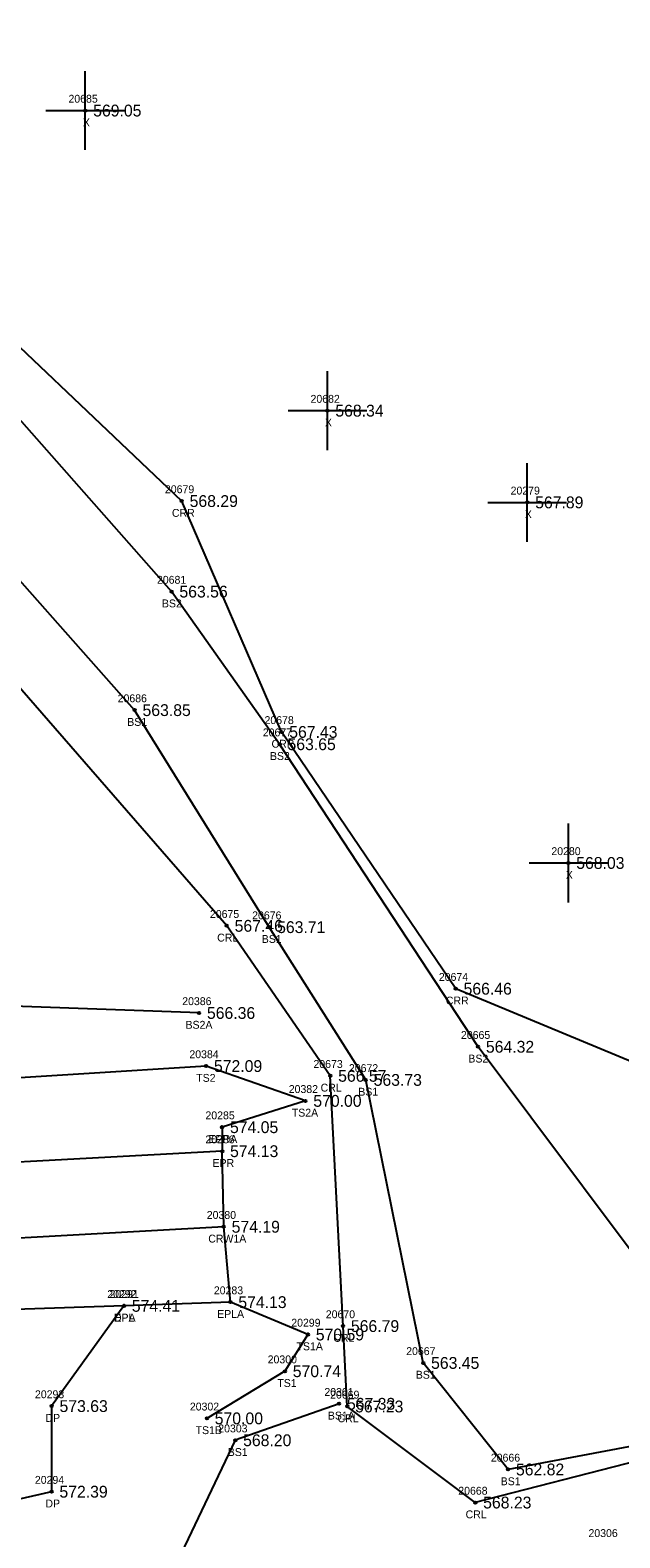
# Model space of a CAD drawing. Extents: x 1530159 to 1531652, y 877045 to 877724.
# Drawn here: x 1530840.9 to 1530915.9, y 877231.5 to 877423 of the extents above; entities that cross this region are included whole.
import ezdxf

# ---------------------------------------------------------------- set-up
doc = ezdxf.new("R2010")
doc.units = 0
for name, color, linetype in [('RD_DTM_BkLn1', 7, 'Continuous'), ('RD_DTM_BkLn2', 7, 'Continuous'), ('RD_DTM_BkLn_txCode', 7, 'Continuous'), ('RD_EX_Driveway', 7, 'Continuous'), ('RD_EX_Driveway_txCode', 7, 'Continuous'), ('RD_EX_H2O', 7, 'Continuous'), ('RD_EX_H2O_txCode', 7, 'Continuous'), ('RD_EX_Misc', 7, 'Continuous'), ('RD_EX_Misc_txCode', 7, 'Continuous'), ('RD_EX_Road', 7, 'Continuous'), ('RD_EX_Road_txCode', 7, 'Continuous'), ('RD_EX_TX_Driveway_ELEV', 7, 'Continuous'), ('RD_EX_TX_H2O_ELEV', 7, 'Continuous'), ('RD_EX_TX_Misc_ELEV', 7, 'Continuous'), ('RD_EX_TX_Road_ELEV', 7, 'Continuous'), ('RD_HC_Survey_ELEV', 7, 'Continuous'), ('RD_HC_Survey_txCode', 7, 'Continuous'), ('RD_SMD_Locator', 7, 'Continuous')]:
    doc.layers.add(name, color=color, linetype=linetype)

msp = doc.modelspace()

# ---------------------------------------------------------------- linework, layer by layer
at = {"layer": 'RD_DTM_BkLn1'}
msp.add_lwpolyline([(1530865.56, 877271.01), (1530814.96, 877268.2), (1530763.15, 877267.89), (1530711.13, 877268.14), (1530659.67, 877269.22), (1530608.85, 877271.65), (1530559.07, 877277.33), (1530509.18, 877284.07), (1530458.44, 877292.62), (1530408.04, 877304.59), (1530358.54, 877316.67), (1530308.57, 877330.02), (1530250.23, 877350.32), (1530188.17, 877372.62)], dxfattribs=at)
at = {"layer": 'RD_DTM_BkLn2'}
for points in [[(1530978.51, 877193.14), (1530957.83, 877217.34), (1530939.69, 877236.27), (1530919.92, 877243.6), (1530901.7, 877240.19), (1530890.91, 877253.72), (1530883.61, 877289.66), (1530871.34, 877309.06), (1530854.23, 877336.62), (1530832.44, 877361.15), (1530819.05, 877374.38), (1530808.85, 877385.69), (1530794.67, 877405.25), (1530798.76, 877416.08), (1530761.4, 877471.05), (1530729.88, 877527.47), (1530702.64, 877561.57), (1530689.57, 877599.12), (1530672.36, 877642.36), (1530634.08, 877679.71), (1530613.02, 877709.76)], [(1530924.53, 877258.32), (1530897.88, 877293.87), (1530872.66, 877332.29), (1530858.92, 877351.67), (1530825.26, 877389.74), (1530809.31, 877429.86), (1530783.89, 877460.41), (1530770.73, 877490.54), (1530744.62, 877534.44), (1530713.25, 877572.12), (1530699.86, 877617.16), (1530688.52, 877646.11), (1530631.13, 877700.3)], [(1530875.94, 877287), (1530863.31, 877291.42), (1530814.58, 877288.36), (1530806.87, 877291), (1530801.27, 877299.11), (1530795.25, 877327.46)], [(1530862.42, 877298.16), (1530816.3, 877299.84), (1530808.21, 877302.66), (1530797.14, 877327.67)], [(1530875.94, 877287), (1530865.35, 877283.66)], [(1530876.26, 877257.33), (1530866.41, 877261.44), (1530865.56, 877271.01), (1530865.36, 877280.61)], [(1530876.26, 877257.33), (1530873.33, 877252.67), (1530863.41, 877246.68)], [(1530880.22, 877248.53), (1530867.02, 877243.9), (1530858.87, 877226.87)]]:
    msp.add_lwpolyline(points, dxfattribs=at)
at = {"layer": 'RD_EX_Driveway'}
msp.add_lwpolyline([(1530852.87, 877260.97), (1530843.68, 877248.24), (1530843.67, 877237.37), (1530832.46, 877234.81), (1530825.81, 877245.01), (1530806.23, 877259.4)], dxfattribs=at)
at = {"layer": 'RD_EX_H2O'}
for points in [[(1530922.5, 877289.86), (1530895.04, 877301.24), (1530872.88, 877333.85), (1530860.22, 877363.17), (1530828.43, 877393.28), (1530808.3, 877433.62), (1530784.24, 877462.07), (1530773.36, 877492.12), (1530746.47, 877535.88), (1530723.52, 877580.98), (1530706.2, 877619.34), (1530689.1, 877649.27), (1530633.62, 877702.51)], [(1530972.1, 877196.48), (1530925.87, 877229.17), (1530918.34, 877241.35), (1530897.53, 877235.99), (1530881.25, 877248.19), (1530880.72, 877258.4), (1530879.1, 877290.18), (1530865.94, 877309.23), (1530832.49, 877347.64), (1530816.44, 877373.18)]]:
    msp.add_lwpolyline(points, dxfattribs=at)
at = {"layer": 'RD_EX_Misc'}
for p, q in [((1530847.96, 877407.76), (1530847.96, 877417.76)), ((1530842.96, 877412.76), (1530852.96, 877412.76)), ((1530878.74, 877369.65), (1530878.74, 877379.65)), ((1530873.74, 877374.65), (1530883.74, 877374.65)), ((1530904.14, 877358), (1530904.14, 877368)), ((1530899.14, 877363), (1530909.14, 877363)), ((1530909.36, 877312.21), (1530909.36, 877322.21)), ((1530904.36, 877317.21), (1530914.36, 877317.21))]:
    msp.add_line(p, q, dxfattribs=at)
at = {"layer": 'RD_EX_Road'}
for points in [[(1530865.35, 877283.66), (1530865.36, 877280.61), (1530815.01, 877277.89), (1530763.54, 877277.33), (1530711.24, 877277.01), (1530660.64, 877277.93), (1530609.51, 877281.74), (1530559.88, 877286.96), (1530511.03, 877294.4), (1530460.35, 877303.35), (1530410.49, 877314.53), (1530361.04, 877326.77), (1530310.59, 877340.83), (1530305.81, 877342.41), (1530288.71, 877347.95), (1530253.55, 877359.27), (1530192.32, 877382.67)], [(1530866.41, 877261.44), (1530852.87, 877260.97), (1530806.23, 877259.4), (1530762.44, 877259.05), (1530711.8, 877259.77), (1530659.89, 877260.87), (1530608.32, 877263.5), (1530557.85, 877268.33), (1530507.29, 877275.71), (1530456.72, 877284.51), (1530406.3, 877294.52), (1530356.75, 877305.76), (1530307.05, 877320.51), (1530246, 877341.34), (1530185.26, 877363.97)]]:
    msp.add_lwpolyline(points, dxfattribs=at)
at = {"layer": 'RD_SMD_Locator'}
for centre in [(1530847.96, 877412.76), (1530878.74, 877374.65), (1530860.22, 877363.17), (1530904.14, 877363), (1530858.92, 877351.67), (1530854.23, 877336.62), (1530872.88, 877333.85), (1530872.66, 877332.29), (1530909.36, 877317.21), (1530865.94, 877309.23), (1530871.34, 877309.06), (1530895.04, 877301.24), (1530862.42, 877298.16), (1530897.88, 877293.87), (1530863.31, 877291.42), (1530879.1, 877290.18), (1530883.61, 877289.66), (1530875.94, 877287), (1530865.35, 877283.66), (1530865.36, 877280.61), (1530865.56, 877271.01), (1530852.87, 877260.97), (1530852.87, 877260.97), (1530866.41, 877261.44), (1530876.26, 877257.33), (1530880.72, 877258.4), (1530890.91, 877253.72), (1530873.33, 877252.67), (1530843.68, 877248.24), (1530880.22, 877248.53), (1530881.25, 877248.19), (1530863.41, 877246.68), (1530867.02, 877243.9), (1530901.7, 877240.19), (1530843.67, 877237.37), (1530897.53, 877235.99)]:
    msp.add_circle(centre, 0.15, dxfattribs=at)

# ---------------------------------------------------------------- texts
at = {"layer": 'RD_DTM_BkLn_txCode'}
for s, p in [('20681', (1530857.07, 877352.67)), ('BS2', (1530857.7, 877349.67)), ('20686', (1530852.07, 877337.62)), ('BS1', (1530853.29, 877334.62)), ('20677', (1530870.52, 877333.29)), ('BS2', (1530871.43, 877330.29)), ('20676', (1530869.17, 877310.06)), ('BS1', (1530870.39, 877307.06)), ('20386', (1530860.28, 877299.16)), ('BS2A', (1530860.7, 877296.16)), ('20665', (1530895.71, 877294.87)), ('20384', (1530861.19, 877292.42)), ('20672', (1530881.47, 877290.66)), ('BS2', (1530896.65, 877291.87)), ('TS2', (1530862.06, 877289.42)), ('20382', (1530873.82, 877288)), ('BS1', (1530882.66, 877287.66)), ('TS2A', (1530874.21, 877285)), ('20299', (1530874.14, 877258.33)), ('TS1A', (1530874.81, 877255.33)), ('20667', (1530888.75, 877254.72)), ('20300', (1530871.14, 877253.67)), ('TS1', (1530872.37, 877250.67)), ('BS1', (1530889.97, 877251.72)), ('20301', (1530878.35, 877249.53)), ('20302', (1530861.25, 877247.68)), ('BS1A', (1530878.79, 877246.53)), ('TS1B', (1530861.98, 877244.68)), ('20303', (1530864.86, 877244.9)), ('BS1', (1530866.07, 877241.9)), ('20666', (1530899.51, 877241.19)), ('BS1', (1530900.76, 877238.19)), ('20306', (1530911.92, 877231.61))]:
    msp.add_text(s, height=1, dxfattribs=at).set_placement(p)
at = {"layer": 'RD_EX_Driveway_txCode'}
for s, p in [('20292', (1530850.75, 877261.97)), ('DPA', (1530851.6, 877258.97)), ('20293', (1530841.56, 877249.24)), ('DP', (1530842.9, 877246.24)), ('20294', (1530841.55, 877238.37)), ('DP', (1530842.89, 877235.37))]:
    msp.add_text(s, height=1, dxfattribs=at).set_placement(p)
at = {"layer": 'RD_EX_H2O_txCode'}
for s, p in [('20679', (1530858.08, 877364.17)), ('CRR', (1530858.97, 877361.17)), ('20678', (1530870.74, 877334.85)), ('CRR', (1530871.63, 877331.85)), ('20675', (1530863.8, 877310.23)), ('CRL', (1530864.72, 877307.23)), ('20674', (1530892.9, 877302.24)), ('CRR', (1530893.79, 877299.24)), ('20673', (1530876.96, 877291.18)), ('CRL', (1530877.87, 877288.18)), ('20670', (1530878.53, 877259.4)), ('CRL', (1530879.49, 877256.4)), ('20669', (1530879.08, 877249.19)), ('CRL', (1530880.02, 877246.19)), ('20668', (1530895.37, 877236.99)), ('CRL', (1530896.3, 877233.99))]:
    msp.add_text(s, height=1, dxfattribs=at).set_placement(p)
at = {"layer": 'RD_EX_Misc_txCode'}
for s, p in [('20685', (1530845.82, 877413.76)), ('X', (1530847.65, 877410.76)), ('20682', (1530876.59, 877375.65)), ('X', (1530878.42, 877372.65)), ('20279', (1530902.02, 877364)), ('X', (1530903.83, 877361)), ('20280', (1530907.2, 877318.21)), ('X', (1530909.04, 877315.21))]:
    msp.add_text(s, height=1, dxfattribs=at).set_placement(p)
at = {"layer": 'RD_EX_Road_txCode'}
for s, p in [('20285', (1530863.23, 877284.66)), ('20286', (1530863.22, 877281.61)), ('EPRA', (1530863.63, 877281.66)), ('EPR', (1530864.13, 877278.61)), ('20291', (1530851.03, 877261.97)), ('20283', (1530864.3, 877262.44)), ('EPL', (1530851.66, 877258.97)), ('EPLA', (1530864.72, 877259.44))]:
    msp.add_text(s, height=1, dxfattribs=at).set_placement(p)
at = {"layer": 'RD_EX_TX_Driveway_ELEV'}
for s, p in [('574.41', (1530853.87, 877260.22)), ('573.63', (1530844.68, 877247.49)), ('572.39', (1530844.67, 877236.62))]:
    msp.add_text(s, height=1.5, dxfattribs=at).set_placement(p)
at = {"layer": 'RD_EX_TX_H2O_ELEV'}
for s, p in [('568.29', (1530861.22, 877362.42)), ('567.43', (1530873.88, 877333.1)), ('567.46', (1530866.94, 877308.48)), ('566.46', (1530896.04, 877300.49)), ('566.57', (1530880.1, 877289.43)), ('566.79', (1530881.72, 877257.65)), ('567.23', (1530882.25, 877247.44)), ('568.23', (1530898.53, 877235.24))]:
    msp.add_text(s, height=1.5, dxfattribs=at).set_placement(p)
at = {"layer": 'RD_EX_TX_Misc_ELEV'}
for s, p in [('569.05', (1530848.96, 877412.01)), ('568.34', (1530879.74, 877373.9)), ('567.89', (1530905.14, 877362.25)), ('563.56', (1530859.92, 877350.92)), ('563.85', (1530855.23, 877335.87)), ('563.65', (1530873.66, 877331.54)), ('568.03', (1530910.36, 877316.46)), ('563.71', (1530872.34, 877308.31)), ('566.36', (1530863.42, 877297.41)), ('564.32', (1530898.88, 877293.12)), ('572.09', (1530864.31, 877290.67)), ('563.73', (1530884.61, 877288.91)), ('570.00', (1530876.94, 877286.25)), ('570.59', (1530877.26, 877256.58)), ('570.74', (1530874.33, 877251.92)), ('563.45', (1530891.91, 877252.97)), ('570.00', (1530864.41, 877245.93)), ('567.33', (1530881.22, 877247.78)), ('568.20', (1530868.02, 877243.15)), ('562.82', (1530902.7, 877239.44))]:
    msp.add_text(s, height=1.5, dxfattribs=at).set_placement(p)
at = {"layer": 'RD_EX_TX_Road_ELEV'}
for s, p in [('574.05', (1530866.35, 877282.91)), ('574.13', (1530866.36, 877279.86)), ('574.41', (1530853.87, 877260.22)), ('574.13', (1530867.41, 877260.69))]:
    msp.add_text(s, height=1.5, dxfattribs=at).set_placement(p)
at = {"layer": 'RD_HC_Survey_ELEV'}
msp.add_text('574.19', height=1.5, dxfattribs=at).set_placement((1530866.56, 877270.26))
at = {"layer": 'RD_HC_Survey_txCode'}
for s, p in [('20380', (1530863.4, 877272.01)), ('CRW1A', (1530863.59, 877269.01))]:
    msp.add_text(s, height=1, dxfattribs=at).set_placement(p)

doc.saveas('drawing.dxf')
